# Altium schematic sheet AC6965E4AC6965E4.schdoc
size 127 x 101 mm
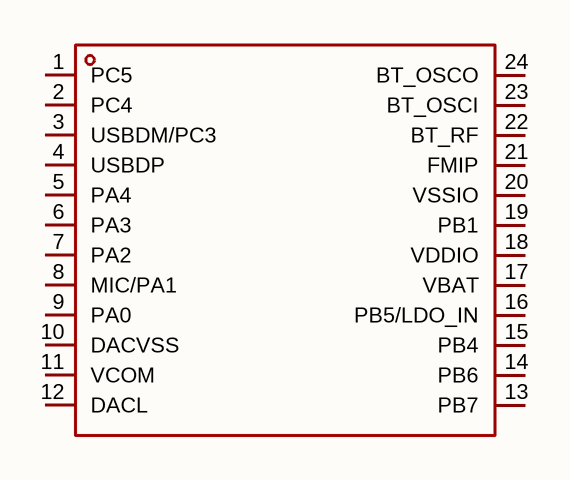
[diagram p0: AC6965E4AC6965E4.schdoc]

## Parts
U?  ac6965e4  [QSOP-24_L8.7-W3.9-P0.64-LS6.0-BL]  (value not drawn)

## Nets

Not connected (* = marked no-connect by the designer): U? 1(PC5) 2(PC4) 3(USBDM/PC3) 4(USBDP) 5(PA4) 6(PA3) 7(PA2) 8(MIC/PA1) 9(PA0) 10(DACVSS) 11(VCOM) 12(DACL) 13(PB7) 14(PB6) 15(PB4) 16(PB5/LDO_IN) 17(VBAT) 18(VDDIO) 19(PB1) 20(VSSIO) 21(FMIP) 22(BT_RF) 23(BT_OSCI) 24(BT_OSCO)

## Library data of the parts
U? = ac6965e4: CPU内核:-;CPU最大主频:160MHz;CPU位数:32 Bit;; Manufacturer: JL(杰理); AddInBom: yes; ModelId: 0d5eb4aa1e904faba2151708d4bb6535; ModelTransform: 339.369,237.007,0,0,0,0,0,0,0; CPU Maximum Speed: 160MHz; Core Size: 32 Bit; ADC (Bit): 16bit; Voltage - Supply: 2.2V~5.5V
